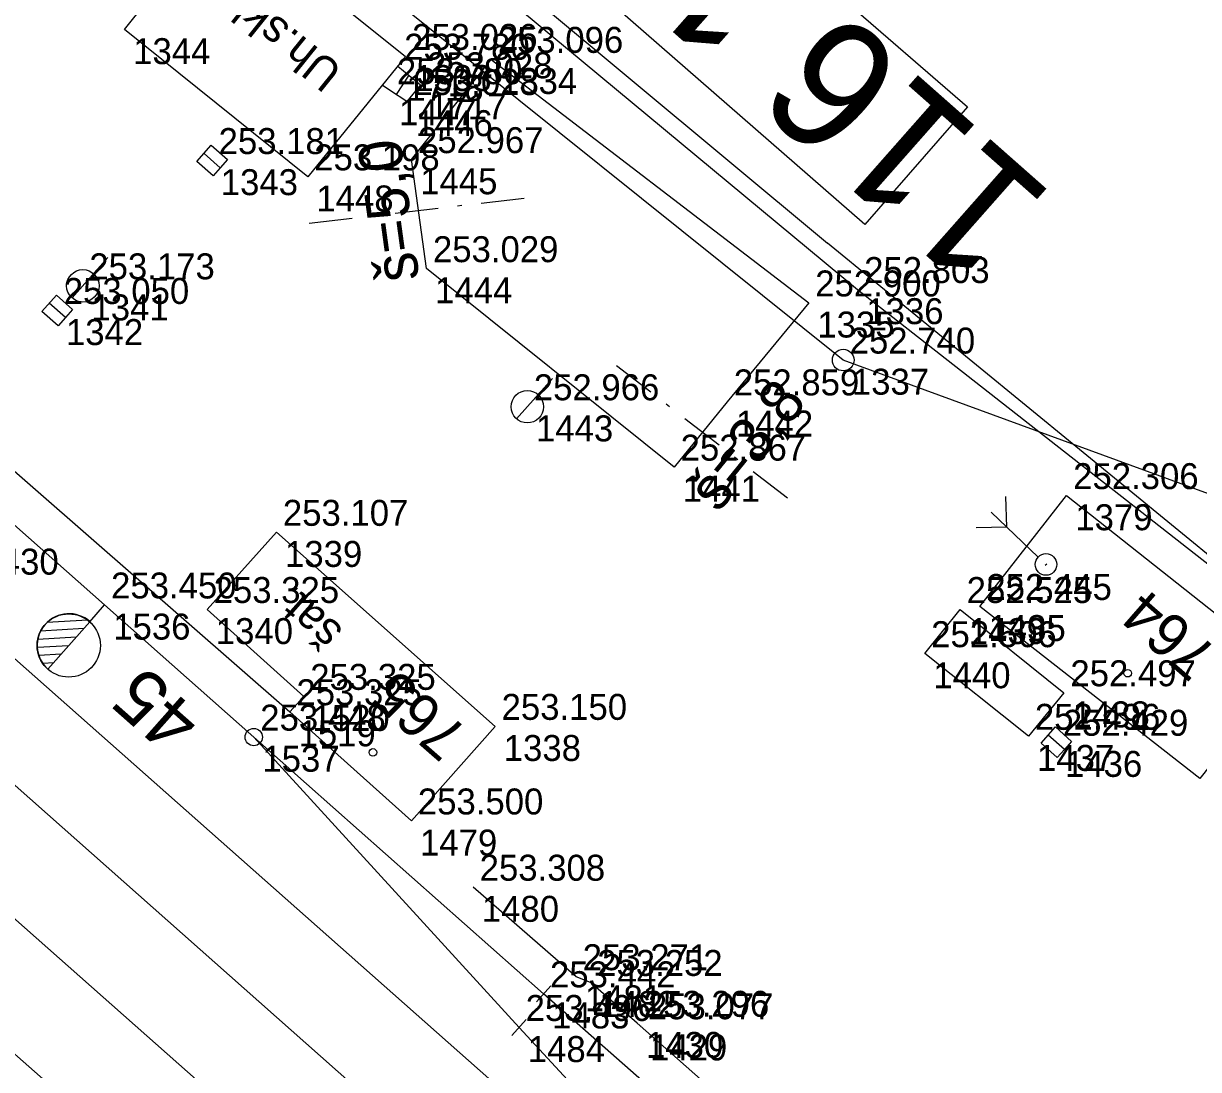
# Model space of a CAD drawing. Extents: x -496688 to -495455, y -1089309 to -1088026.
# Drawn here: x -496308.4 to -496254, y -1088327.4 to -1088279.1 of the extents above; entities that cross this region are included whole.
import ezdxf

# ---------------------------------------------------------------- set-up
doc = ezdxf.new("R2010")
doc.units = 0
for name, color, linetype in [('Vrstva 1', 7, 'Continuous'), ('Vrstva 13', 7, 'Continuous'), ('Vrstva 16', 7, 'Continuous'), ('Vrstva 17', 7, 'Continuous'), ('Vrstva 2', 7, 'Continuous'), ('Vrstva 20', 7, 'Continuous'), ('Vrstva 23', 7, 'Continuous'), ('Vrstva 29', 7, 'Continuous'), ('Vrstva 36', 7, 'Continuous'), ('Vrstva 43', 7, 'Continuous'), ('Vrstva 47', 7, 'Continuous'), ('Vrstva 50', 7, 'Continuous'), ('Vrstva 55', 7, 'Continuous'), ('Vrstva 57', 7, 'Continuous'), ('Vrstva 59', 7, 'Continuous'), ('Vrstva 60', 7, 'Continuous'), ('Vrstva 61', 7, 'Continuous'), ('Vrstva 7', 7, 'Continuous')]:
    doc.layers.add(name, color=color, linetype=linetype)

msp = doc.modelspace()

# ---------------------------------------------------------------- linework, layer by layer
at = {"layer": 'Vrstva 1'}
for points in [[(-496070.911, -1088512.268), (-496081.102, -1088503.198), (-496099.259, -1088487.166), (-496120.522, -1088468.335), (-496158.247, -1088435.006), (-496187.973, -1088408.831), (-496214.925, -1088385.093), (-496284.321, -1088323.939), (-496297.716, -1088312.071), (-496304.611, -1088305.962), (-496373.694, -1088244.754), (-496406.269, -1088215.906), (-496420.876, -1088202.973), (-496448.215, -1088178.792), (-496461.979, -1088166.666), (-496475.803, -1088154.487), (-496489.993, -1088142.049), (-496510.493, -1088124.003), (-496531.571, -1088105.326), (-496552.766, -1088086.454)], [(-496130.335, -1088478.506), (-496167.718, -1088445.393), (-496197.21, -1088419.263), (-496225.506, -1088394.245), (-496256.508, -1088366.77), (-496292.165, -1088335.176), (-496318.816, -1088311.581), (-496365.129, -1088270.575), (-496383.01, -1088254.728), (-496415.027, -1088226.378), (-496431.39, -1088211.922), (-496455.799, -1088190.339), (-496486.852, -1088162.818), (-496500.339, -1088150.888), (-496509.328, -1088142.943), (-496518.778, -1088134.592), (-496521.474, -1088132.196), (-496532.365, -1088122.544), (-496541.804, -1088114.181), (-496568.02, -1088091.056), (-496570.27, -1088089.072)], [(-496133.331, -1088482.129), (-496170.85, -1088448.892), (-496201.292, -1088421.94), (-496228.817, -1088397.564), (-496259.484, -1088370.356), (-496295.495, -1088338.436), (-496321.941, -1088315.102), (-496368.146, -1088274.115), (-496386.312, -1088258.02), (-496419.129, -1088229.028), (-496434.711, -1088215.25), (-496459.03, -1088193.761), (-496488.382, -1088167.801), (-496490.273, -1088166.162), (-496503.436, -1088154.084), (-496512.25, -1088145.132), (-496520.705, -1088135.775), (-496522.729, -1088133.535), (-496532.365, -1088122.544)], [(-496127.249, -1088474.987), (-496164.633, -1088441.927), (-496194.156, -1088415.812), (-496222.417, -1088390.782), (-496253.66, -1088363.085), (-496288.931, -1088331.871), (-496315.822, -1088308.059), (-496361.867, -1088267.294), (-496379.852, -1088251.348), (-496411.943, -1088222.928), (-496452.422, -1088187.112), (-496474.075, -1088168.05), (-496483.743, -1088160.007), (-496494.217, -1088152.984), (-496499.298, -1088149.577), (-496509.328, -1088142.943)], [(-496036.319, -1088548.972), (-496045.785, -1088540.649), (-496064.628, -1088524.057), (-496083.67, -1088507.239), (-496103.021, -1088490.147), (-496124.246, -1088471.39), (-496161.572, -1088438.415), (-496191.039, -1088412.432), (-496219.148, -1088387.64), (-496250.551, -1088359.908), (-496261.473, -1088350.285), (-496268.374, -1088344.182), (-496281.78, -1088332.327), (-496285.233, -1088329.281), (-496312.832, -1088304.86), (-496359.365, -1088263.75), (-496376.965, -1088248.145), (-496408.98, -1088219.799), (-496424.444, -1088206.174), (-496431.338, -1088200.064), (-496444.668, -1088188.252)], [(-496268.374, -1088344.182), (-496280.588, -1088330.754), (-496285.448, -1088325.493), (-496297.716, -1088312.071)]]:
    msp.add_lwpolyline(points, dxfattribs=at)
at = {"layer": 'Vrstva 13'}
msp.add_lwpolyline([(-496084.271, -1088485.989), (-496090.463, -1088492.67), (-496120.05, -1088466.536), (-496158.385, -1088432.661), (-496186.994, -1088407.463), (-496213.856, -1088383.727), (-496261.077, -1088342.032), (-496279.986, -1088325.301), (-496282.142, -1088323.411), (-496282.81, -1088323.146), (-496287.572, -1088319.009)], dxfattribs=at)
at = {"layer": 'Vrstva 16'}
msp.add_lwpolyline([(-496342.617, -1088269.783), (-496338.066, -1088273.984), (-496326.557, -1088284.251), (-496296.044, -1088310.897)], dxfattribs=at)
at = {"layer": 'Vrstva 17'}
for p, q in [((-496285.213, -1088287.165), (-496287.2, -1088287.396)), ((-496289.186, -1088287.627), (-496291.174, -1088287.859)), ((-496288.094, -1088287.5), (-496288.293, -1088287.523)), ((-496293.16, -1088288.09), (-496295.147, -1088288.321)), ((-496292.067, -1088287.963), (-496292.266, -1088287.986)), ((-496279.366, -1088296.127), (-496280.947, -1088294.902)), ((-496278.497, -1088296.8), (-496278.655, -1088296.678)), ((-496276.205, -1088298.576), (-496277.785, -1088297.352)), ((-496275.335, -1088299.25), (-496275.493, -1088299.128)), ((-496273.043, -1088301.026), (-496274.624, -1088299.801))]:
    msp.add_line(p, q, dxfattribs=at)
for points in [[(-496307.762, -1088259.861), (-496269.8, -1088291.38), (-496248.423, -1088308.125)], [(-496286.736, -1088280.739), (-496272.062, -1088291.999), (-496275.827, -1088296.574), (-496278.283, -1088299.59), (-496289.732, -1088290.415), (-496290.422, -1088285.375), (-496286.736, -1088280.739)]]:
    msp.add_lwpolyline(points, dxfattribs=at)
at = {"layer": 'Vrstva 2'}
for p, q in [((-496305.29, -1088306.734), (-496304.611, -1088305.962)), ((-496305.381, -1088306.666), (-496307.276, -1088306.78)), ((-496305.291, -1088306.734), (-496307.232, -1088308.925)), ((-496307.232, -1088308.925), (-496305.292, -1088306.734)), ((-496305.292, -1088306.734), (-496305.291, -1088306.734)), ((-496305.924, -1088307.449), (-496307.697, -1088307.557)), ((-496305.573, -1088307.053), (-496307.567, -1088307.174)), ((-496306.277, -1088307.846), (-496307.718, -1088307.934)), ((-496306.628, -1088308.243), (-496307.641, -1088308.305)), ((-496306.98, -1088308.641), (-496307.456, -1088308.67)), ((-496284.652, -1088324.313), (-496283.99, -1088323.565)), ((-496285.779, -1088325.867), (-496285.117, -1088325.119))]:
    msp.add_line(p, q, dxfattribs=at)
for points in [[(-496304.611, -1088305.962), (-496297.716, -1088312.071), (-496284.321, -1088323.939)], [(-496297.716, -1088312.071), (-496285.448, -1088325.493)]]:
    msp.add_lwpolyline(points, dxfattribs=at)
for centre, radius in [((-496306.268, -1088307.835), 1.462), ((-496297.716, -1088312.071), 0.4)]:
    msp.add_circle(centre, radius, dxfattribs=at)
msp.add_arc((-496306.261, -1088307.83), 1.464, 48.5001, 228.4609, dxfattribs=at)
at = {"layer": 'Vrstva 20'}
msp.add_lwpolyline([(-496266.702, -1088308.213), (-496265.06, -1088306.171), (-496260.267, -1088310.02), (-496261.908, -1088312.033), (-496266.702, -1088308.213)], dxfattribs=at)
at = {"layer": 'Vrstva 23'}
for p, q in [((-496291.062, -1088281.055), (-496290.006, -1088281.913)), ((-496291.398, -1088282.187), (-496291.779, -1088281.936)), ((-496290.549, -1088281.472), (-496291.135, -1088282.36)), ((-496290.006, -1088281.913), (-496290.637, -1088282.689)), ((-496290.637, -1088282.689), (-496291.398, -1088282.187))]:
    msp.add_line(p, q, dxfattribs=at)
for points in [[(-496312.479, -1088268.372), (-496309.984, -1088265.171), (-496290.696, -1088280.604), (-496295.221, -1088286.171), (-496303.69, -1088279.36), (-496301.745, -1088276.917), (-496312.479, -1088268.372)], [(-496264.151, -1088306.031), (-496260.139, -1088300.907), (-496250.976, -1088308.155), (-496250.852, -1088307.998), (-496249.848, -1088308.792), (-496253.98, -1088313.979), (-496264.151, -1088306.031)], [(-496299.87, -1088306.17), (-496296.67, -1088302.603), (-496286.559, -1088311.573), (-496290.43, -1088315.946), (-496296.044, -1088310.897), (-496295.404, -1088310.186), (-496299.87, -1088306.17)]]:
    msp.add_lwpolyline(points, dxfattribs=at)
at = {"layer": 'Vrstva 29'}
msp.add_lwpolyline([(-496228.726, -1088272.089), (-496242.207, -1088304.985), (-496270.468, -1088294.64), (-496292.916, -1088276.634), (-496314.625, -1088256.754), (-496338.738, -1088235.152), (-496372.173, -1088205.903), (-496403.1, -1088180.315), (-496426.737, -1088162.268), (-496430.704, -1088173.66)], dxfattribs=at)
at = {"layer": 'Vrstva 36'}
msp.add_circle((-496270.468, -1088294.64), 0.5, dxfattribs=at)
at = {"layer": 'Vrstva 43'}
for points in [[(-496299.266, -1088285.749), (-496299.597, -1088286.123), (-496300.346, -1088285.46), (-496299.683, -1088284.711), (-496298.934, -1088285.374), (-496299.266, -1088285.749), (-496300.014, -1088285.085)], [(-496306.424, -1088292.679), (-496306.755, -1088293.053), (-496307.504, -1088292.39), (-496306.841, -1088291.641), (-496306.092, -1088292.304), (-496306.424, -1088292.679), (-496307.172, -1088292.015)], [(-496260.242, -1088312.64), (-496260.574, -1088313.015), (-496261.323, -1088312.352), (-496260.66, -1088311.603), (-496259.911, -1088312.266), (-496260.242, -1088312.64), (-496260.992, -1088311.978)]]:
    msp.add_lwpolyline(points, dxfattribs=at)
at = {"layer": 'Vrstva 47'}
for p, q in [((-496306.114, -1088291.77), (-496304.457, -1088289.898)), ((-496285.567, -1088297.361), (-496283.91, -1088295.489))]:
    msp.add_line(p, q, dxfattribs=at)
for centre in [(-496305.617, -1088291.208), (-496285.07, -1088296.799)]:
    msp.add_circle(centre, 0.75, dxfattribs=at)
at = {"layer": 'Vrstva 50'}
for p, q in [((-496262.904, -1088302.366), (-496262.943, -1088300.941)), ((-496261.456, -1088303.745), (-496263.628, -1088301.676)), ((-496262.904, -1088302.366), (-496264.318, -1088302.4)), ((-496261.129, -1088304.126), (-496261.059, -1088304.054))]:
    msp.add_line(p, q, dxfattribs=at)
msp.add_circle((-496261.094, -1088304.09), 0.5, dxfattribs=at)
at = {"layer": 'Vrstva 55'}
for p, q in [((-496292.05, -1088259.28), (-496264.72, -1088282.93)), ((-496269.47, -1088288.37), (-496296.7, -1088264.61)), ((-496285.12, -1088277.63), (-496271.2, -1088289.24)), ((-496264.72, -1088282.93), (-496269.47, -1088288.37)), ((-496248.36, -1088307.94), (-496271.2, -1088289.24))]:
    msp.add_line(p, q, dxfattribs=at)
at = {"layer": 'Vrstva 59'}
for centre in [(-496257.314, -1088309.116), (-496292.208, -1088312.778)]:
    msp.add_circle(centre, 0.175, dxfattribs=at)
at = {"layer": 'Vrstva 60'}
for p, q in [((-496303.69, -1088279.36), (-496303.69, -1088279.36)), ((-496303.69, -1088279.36), (-496303.69, -1088279.36)), ((-496290.696, -1088280.604), (-496290.696, -1088280.604)), ((-496290.696, -1088280.604), (-496290.696, -1088280.604)), ((-496286.736, -1088280.739), (-496286.736, -1088280.739)), ((-496286.736, -1088280.739), (-496286.736, -1088280.739)), ((-496291.062, -1088281.055), (-496291.062, -1088281.055)), ((-496291.062, -1088281.055), (-496291.062, -1088281.055)), ((-496290.006, -1088281.913), (-496290.006, -1088281.913)), ((-496290.006, -1088281.913), (-496290.006, -1088281.913)), ((-496291.398, -1088282.187), (-496291.398, -1088282.187)), ((-496291.398, -1088282.187), (-496291.398, -1088282.187)), ((-496290.637, -1088282.689), (-496290.637, -1088282.689)), ((-496290.637, -1088282.689), (-496290.637, -1088282.689)), ((-496299.64, -1088285.417), (-496299.64, -1088285.417)), ((-496299.64, -1088285.417), (-496299.64, -1088285.417)), ((-496290.422, -1088285.375), (-496290.422, -1088285.375)), ((-496290.422, -1088285.375), (-496290.422, -1088285.375)), ((-496295.221, -1088286.171), (-496295.221, -1088286.171)), ((-496295.221, -1088286.171), (-496295.221, -1088286.171)), ((-496289.732, -1088290.415), (-496289.732, -1088290.415)), ((-496289.732, -1088290.415), (-496289.732, -1088290.415)), ((-496305.617, -1088291.208), (-496305.617, -1088291.208)), ((-496305.617, -1088291.208), (-496305.617, -1088291.208)), ((-496269.8, -1088291.38), (-496269.8, -1088291.38)), ((-496269.8, -1088291.38), (-496269.8, -1088291.38)), ((-496272.062, -1088291.999), (-496272.062, -1088291.999)), ((-496272.062, -1088291.999), (-496272.062, -1088291.999)), ((-496306.798, -1088292.347), (-496306.798, -1088292.347)), ((-496306.798, -1088292.347), (-496306.798, -1088292.347)), ((-496270.468, -1088294.64), (-496270.468, -1088294.64)), ((-496270.468, -1088294.64), (-496270.468, -1088294.64)), ((-496275.827, -1088296.574), (-496275.827, -1088296.574)), ((-496275.827, -1088296.574), (-496275.827, -1088296.574)), ((-496285.07, -1088296.799), (-496285.07, -1088296.799)), ((-496285.07, -1088296.799), (-496285.07, -1088296.799)), ((-496278.283, -1088299.59), (-496278.283, -1088299.59)), ((-496278.283, -1088299.59), (-496278.283, -1088299.59)), ((-496260.139, -1088300.907), (-496260.139, -1088300.907)), ((-496260.139, -1088300.907), (-496260.139, -1088300.907)), ((-496296.67, -1088302.603), (-496296.67, -1088302.603)), ((-496296.67, -1088302.603), (-496296.67, -1088302.603)), ((-496304.611, -1088305.962), (-496304.611, -1088305.962)), ((-496304.611, -1088305.962), (-496304.611, -1088305.962)), ((-496299.87, -1088306.17), (-496299.87, -1088306.17)), ((-496299.87, -1088306.17), (-496299.87, -1088306.17)), ((-496265.06, -1088306.171), (-496265.06, -1088306.171)), ((-496265.06, -1088306.171), (-496265.06, -1088306.171)), ((-496264.151, -1088306.031), (-496264.151, -1088306.031)), ((-496264.151, -1088306.031), (-496264.151, -1088306.031)), ((-496266.702, -1088308.213), (-496266.702, -1088308.213)), ((-496266.702, -1088308.213), (-496266.702, -1088308.213)), ((-496295.404, -1088310.186), (-496295.404, -1088310.186)), ((-496295.404, -1088310.186), (-496295.404, -1088310.186)), ((-496260.267, -1088310.02), (-496260.267, -1088310.02)), ((-496260.267, -1088310.02), (-496260.267, -1088310.02)), ((-496296.044, -1088310.897), (-496296.044, -1088310.897)), ((-496296.044, -1088310.897), (-496296.044, -1088310.897)), ((-496286.559, -1088311.573), (-496286.559, -1088311.573)), ((-496286.559, -1088311.573), (-496286.559, -1088311.573)), ((-496297.716, -1088312.071), (-496297.716, -1088312.071)), ((-496297.716, -1088312.071), (-496297.716, -1088312.071)), ((-496261.908, -1088312.033), (-496261.908, -1088312.033)), ((-496261.908, -1088312.033), (-496261.908, -1088312.033)), ((-496260.617, -1088312.309), (-496260.617, -1088312.309)), ((-496260.617, -1088312.309), (-496260.617, -1088312.309)), ((-496290.43, -1088315.946), (-496290.43, -1088315.946)), ((-496290.43, -1088315.946), (-496290.43, -1088315.946)), ((-496287.572, -1088319.009), (-496287.572, -1088319.009)), ((-496287.572, -1088319.009), (-496287.572, -1088319.009)), ((-496282.81, -1088323.146), (-496282.81, -1088323.146)), ((-496282.81, -1088323.146), (-496282.81, -1088323.146)), ((-496282.142, -1088323.411), (-496282.142, -1088323.411)), ((-496282.142, -1088323.411), (-496282.142, -1088323.411)), ((-496284.321, -1088323.939), (-496284.321, -1088323.939)), ((-496284.321, -1088323.939), (-496284.321, -1088323.939)), ((-496279.986, -1088325.301), (-496279.986, -1088325.301)), ((-496279.986, -1088325.301), (-496279.986, -1088325.301)), ((-496285.448, -1088325.493), (-496285.448, -1088325.493)), ((-496285.448, -1088325.493), (-496285.448, -1088325.493)), ((-496279.798, -1088325.415), (-496279.798, -1088325.415)), ((-496279.798, -1088325.415), (-496279.798, -1088325.415))]:
    msp.add_line(p, q, dxfattribs=at)

# ---------------------------------------------------------------- texts
at = {"layer": 'Vrstva 17'}
for s, rotation, p in [('š=5,0', 97.7955, (-496290.054, -1088290.885)), ('š=3,8', 51.0026, (-496276.254, -1088301.741))]:
    msp.add_text(s, height=2, rotation=rotation, dxfattribs=at).set_placement(p)
at = {"layer": 'Vrstva 2'}
msp.add_text('45', height=2.5, rotation=138.4805, dxfattribs=at).set_placement((-496300.011, -1088311.149))
at = {"layer": 'Vrstva 23'}
for s, rotation, p in [('Uh.skl.', 141.1928, (-496293.535, -1088281.172)), ('šat.', 138.5141, (-496293.528, -1088307.088))]:
    msp.add_text(s, height=1.5, rotation=rotation, dxfattribs=at).set_placement(p)
at = {"layer": 'Vrstva 57'}
for s, p in [('764', (-496253.089, -1088308.081)), ('765', (-496287.739, -1088311.793))]:
    msp.add_text(s, height=2, rotation=138.8931, dxfattribs=at).set_placement(p)
at = {"layer": 'Vrstva 60'}
for s, p in [('1344', (-496303.29, -1088280.96)), ('1344', (-496303.29, -1088280.96)), ('1333', (-496290.296, -1088282.204)), ('1333', (-496290.296, -1088282.204)), ('1334', (-496286.336, -1088282.339)), ('1334', (-496286.336, -1088282.339)), ('1718', (-496290.662, -1088282.655)), ('1718', (-496290.662, -1088282.655)), ('1717', (-496289.606, -1088283.513)), ('1717', (-496289.606, -1088283.513)), ('1447', (-496290.998, -1088283.787)), ('1447', (-496290.998, -1088283.787)), ('1446', (-496290.237, -1088284.289)), ('1446', (-496290.237, -1088284.289)), ('1343', (-496299.24, -1088287.017)), ('1343', (-496299.24, -1088287.017)), ('1445', (-496290.022, -1088286.975)), ('1445', (-496290.022, -1088286.975)), ('1448', (-496294.821, -1088287.771)), ('1448', (-496294.821, -1088287.771)), ('1444', (-496289.332, -1088292.015)), ('1444', (-496289.332, -1088292.015)), ('1341', (-496305.217, -1088292.808)), ('1341', (-496305.217, -1088292.808)), ('1336', (-496269.4, -1088292.98)), ('1336', (-496269.4, -1088292.98)), ('1342', (-496306.398, -1088293.947)), ('1342', (-496306.398, -1088293.947)), ('1335', (-496271.662, -1088293.599)), ('1335', (-496271.662, -1088293.599)), ('1337', (-496270.068, -1088296.24)), ('1337', (-496270.068, -1088296.24)), ('1442', (-496275.427, -1088298.174)), ('1442', (-496275.427, -1088298.174)), ('1443', (-496284.67, -1088298.399)), ('1443', (-496284.67, -1088298.399)), ('1441', (-496277.883, -1088301.19)), ('1441', (-496277.883, -1088301.19)), ('1379', (-496259.739, -1088302.507)), ('1379', (-496259.739, -1088302.507)), ('1339', (-496296.27, -1088304.203)), ('1339', (-496296.27, -1088304.203)), ('1536', (-496304.211, -1088307.562)), ('1536', (-496304.211, -1088307.562)), ('1340', (-496299.47, -1088307.77)), ('1340', (-496299.47, -1088307.77)), ('1439', (-496264.66, -1088307.771)), ('1439', (-496264.66, -1088307.771)), ('1435', (-496263.751, -1088307.631)), ('1435', (-496263.751, -1088307.631)), ('1440', (-496266.302, -1088309.813)), ('1440', (-496266.302, -1088309.813)), ('1520', (-496295.004, -1088311.786)), ('1520', (-496295.004, -1088311.786)), ('1438', (-496259.867, -1088311.62)), ('1438', (-496259.867, -1088311.62)), ('1519', (-496295.644, -1088312.497)), ('1519', (-496295.644, -1088312.497)), ('1338', (-496286.159, -1088313.173)), ('1338', (-496286.159, -1088313.173)), ('1537', (-496297.316, -1088313.671)), ('1537', (-496297.316, -1088313.671)), ('1437', (-496261.508, -1088313.633)), ('1437', (-496261.508, -1088313.633)), ('1436', (-496260.217, -1088313.909)), ('1436', (-496260.217, -1088313.909)), ('1479', (-496290.03, -1088317.546)), ('1479', (-496290.03, -1088317.546)), ('1480', (-496287.172, -1088320.609)), ('1480', (-496287.172, -1088320.609)), ('1481', (-496282.41, -1088324.746)), ('1481', (-496282.41, -1088324.746)), ('1482', (-496281.742, -1088325.011)), ('1482', (-496281.742, -1088325.011)), ('1483', (-496283.921, -1088325.539)), ('1483', (-496283.921, -1088325.539)), ('1484', (-496285.048, -1088327.093)), ('1484', (-496285.048, -1088327.093)), ('1430', (-496279.586, -1088326.901)), ('1430', (-496279.586, -1088326.901)), ('1429', (-496279.398, -1088327.015)), ('1429', (-496279.398, -1088327.015))]:
    msp.add_text(s, height=1.2, dxfattribs=at).set_placement(p)
at = {"layer": 'Vrstva 61'}
for s, p in [('253.026', (-496290.396, -1088280.304)), ('253.026', (-496290.396, -1088280.304)), ('253.096', (-496286.436, -1088280.439)), ('253.096', (-496286.436, -1088280.439)), ('253.780', (-496290.762, -1088280.755)), ('253.780', (-496290.762, -1088280.755)), ('253.780', (-496291.098, -1088281.887)), ('253.780', (-496291.098, -1088281.887)), ('253.028', (-496289.706, -1088281.613)), ('253.028', (-496289.706, -1088281.613)), ('253.028', (-496290.337, -1088282.389)), ('253.028', (-496290.337, -1088282.389)), ('253.181', (-496299.34, -1088285.117)), ('253.181', (-496299.34, -1088285.117)), ('252.967', (-496290.122, -1088285.075)), ('252.967', (-496290.122, -1088285.075)), ('253.198', (-496294.921, -1088285.871)), ('253.198', (-496294.921, -1088285.871)), ('253.029', (-496289.432, -1088290.115)), ('253.029', (-496289.432, -1088290.115)), ('253.173', (-496305.317, -1088290.908)), ('253.173', (-496305.317, -1088290.908)), ('252.803', (-496269.5, -1088291.08)), ('252.803', (-496269.5, -1088291.08)), ('252.900', (-496271.762, -1088291.699)), ('252.900', (-496271.762, -1088291.699)), ('253.050', (-496306.498, -1088292.047)), ('253.050', (-496306.498, -1088292.047)), ('252.740', (-496270.168, -1088294.34)), ('252.740', (-496270.168, -1088294.34)), ('252.966', (-496284.77, -1088296.499)), ('252.966', (-496284.77, -1088296.499)), ('252.859', (-496275.527, -1088296.274)), ('252.859', (-496275.527, -1088296.274)), ('252.867', (-496277.983, -1088299.29)), ('252.867', (-496277.983, -1088299.29)), ('252.306', (-496259.839, -1088300.607)), ('252.306', (-496259.839, -1088300.607)), ('253.107', (-496296.37, -1088302.303)), ('253.107', (-496296.37, -1088302.303)), ('253.430', (-496312.532, -1088304.56)), ('253.430', (-496312.532, -1088304.56)), ('253.450', (-496304.311, -1088305.662)), ('253.450', (-496304.311, -1088305.662)), ('253.325', (-496299.57, -1088305.87)), ('253.325', (-496299.57, -1088305.87)), ('252.525', (-496264.76, -1088305.871)), ('252.525', (-496264.76, -1088305.871)), ('252.445', (-496263.851, -1088305.731)), ('252.445', (-496263.851, -1088305.731)), ('252.506', (-496266.402, -1088307.913)), ('252.506', (-496266.402, -1088307.913)), ('252.497', (-496259.967, -1088309.72)), ('252.497', (-496259.967, -1088309.72)), ('253.325', (-496295.104, -1088309.886)), ('253.325', (-496295.104, -1088309.886)), ('253.325', (-496295.744, -1088310.597)), ('253.325', (-496295.744, -1088310.597)), ('253.150', (-496286.259, -1088311.273)), ('253.150', (-496286.259, -1088311.273)), ('253.448', (-496297.416, -1088311.771)), ('253.448', (-496297.416, -1088311.771)), ('252.496', (-496261.608, -1088311.733)), ('252.496', (-496261.608, -1088311.733)), ('252.429', (-496260.317, -1088312.009)), ('252.429', (-496260.317, -1088312.009)), ('253.500', (-496290.13, -1088315.646)), ('253.500', (-496290.13, -1088315.646)), ('253.308', (-496287.272, -1088318.709)), ('253.308', (-496287.272, -1088318.709)), ('253.271', (-496282.51, -1088322.846)), ('253.271', (-496282.51, -1088322.846)), ('253.252', (-496281.842, -1088323.111)), ('253.252', (-496281.842, -1088323.111)), ('253.442', (-496284.021, -1088323.639)), ('253.442', (-496284.021, -1088323.639)), ('253.496', (-496285.148, -1088325.193)), ('253.496', (-496285.148, -1088325.193)), ('253.296', (-496279.686, -1088325.001)), ('253.296', (-496279.686, -1088325.001)), ('253.077', (-496279.498, -1088325.115)), ('253.077', (-496279.498, -1088325.115))]:
    msp.add_text(s, height=1.2, dxfattribs=at).set_placement(p)
at = {"layer": 'Vrstva 7'}
msp.add_text('116.1', height=6, rotation=138.557, dxfattribs=at).set_placement((-496260.617, -1088287.12))

doc.saveas('drawing.dxf')
